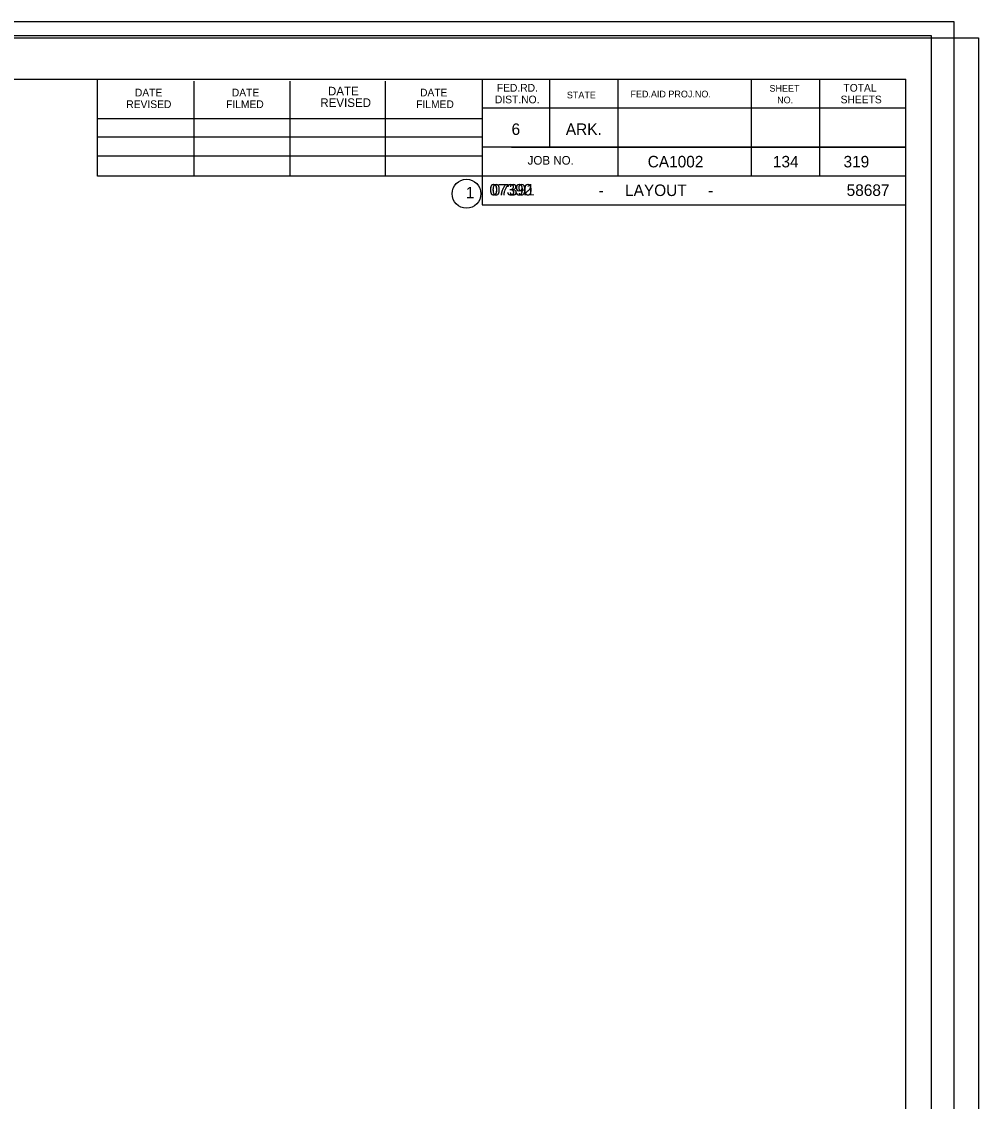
# Model space of a CAD drawing. Extents: x -290 to 969, y 225 to 885.
# Drawn here: x 451.9 to 743.9, y 555 to 884.6 of the extents above; entities that cross this region are included whole.
import ezdxf

# ---------------------------------------------------------------- set-up
doc = ezdxf.new("R2010")
doc.units = 0
for name, color, linetype in [('border', 7, 'Continuous'), ('Border 2660-Hwy18 - Level 62', 7, 'Continuous'), ('Border 2660-Hwy18 - Level 63', 7, 'Continuous'), ('Border 2660-Hwy18 - Text', 7, 'Continuous'), ('Bridge No BLFR', 7, 'Continuous'), ('Bridge No BLO', 7, 'Continuous'), ('Bridge No Ditch 81', 7, 'Continuous'), ('Level 62 PDF', 7, 'Continuous'), ('Text', 7, 'Continuous'), ('Title Text', 7, 'Continuous')]:
    doc.layers.add(name, color=color, linetype=linetype)

msp = doc.modelspace()

# ---------------------------------------------------------------- linework, layer by layer
at = {"layer": 'border'}
for p, q in [((-238.51, 867.08), (721.82, 867.08)), ((475.04, 837.45), (475.04, 867.08)), ((592.51, 867.08), (592.51, 828.7)), ((613.03, 867.08), (613.03, 846.27)), ((633.88, 867.08), (633.88, 837.45)), ((674.59, 867.08), (674.59, 837.45)), ((695.43, 867.08), (695.43, 837.45)), ((721.82, 250.72), (721.82, 867.08)), ((504.6, 837.45), (504.6, 866.5)), ((533.9, 837.45), (533.9, 866.5)), ((562.92, 837.45), (562.92, 866.5)), ((721.82, 858.26), (592.51, 858.26)), ((721.82, 858.33), (721.82, 858.33)), ((475.04, 855.02), (592.51, 855.02)), ((475.04, 849.44), (592.51, 849.44)), ((721.82, 846.27), (592.51, 846.27)), ((601.4, 846.27), (721.82, 846.27)), ((475.04, 837.45), (475.04, 843.64)), ((475.04, 843.64), (592.51, 843.64)), ((721.82, 837.45), (475.04, 837.45)), ((592.51, 828.7), (721.82, 828.7))]:
    msp.add_line(p, q, dxfattribs=at)
msp.add_circle((587.68, 832.1), 4.4, dxfattribs=at)
at = {"layer": 'Border 2660-Hwy18 - Level 62'}
msp.add_lwpolyline([(-287.11, 884.65), (736.44, 884.65), (736.44, 230.36), (-287.11, 230.36)], close=True, dxfattribs=at)
at = {"layer": 'Border 2660-Hwy18 - Level 63'}
msp.add_lwpolyline([(-290.45, 880.36), (729.54, 880.36), (729.54, 239.27), (-290.45, 239.27)], close=True, dxfattribs=at)
at = {"layer": 'Level 62 PDF'}
msp.add_lwpolyline([(-279.61, 879.65), (743.94, 879.65), (743.94, 225.36), (-279.61, 225.36)], close=True, dxfattribs=at)

# ---------------------------------------------------------------- texts
at = {"layer": 'Border 2660-Hwy18 - Text'}
for s, height, p in [('DATE', 2.345, (486.46, 861.82)), ('DATE', 2.345, (516.05, 861.82)), ('DATE', 2.637, (545.39, 862.11)), ('DATE', 2.345, (573.5, 861.82)), ('FED.RD.', 2.345, (596.94, 863.26)), ('SHEET', 2.052, (680.17, 863.26)), ('TOTAL', 2.345, (702.74, 863.26)), ('REVISED', 2.345, (483.83, 858.26)), ('FILMED', 2.345, (514.28, 858.26)), ('REVISED', 2.637, (543.05, 858.58)), ('FILMED', 2.345, (572.32, 858.26)), ('DIST.NO.', 2.345, (596.36, 859.7)), ('STATE', 2.052, (618.32, 861.21)), ('FED.AID PROJ.NO.', 2.0516, (637.73, 861.5)), ('NO.', 2.052, (682.51, 859.7)), ('SHEETS', 2.345, (701.88, 859.7)), ('6', 3.52, (601.44, 850.05)), ('ARK.', 3.516, (618, 850.05)), ('JOB NO.', 2.637, (606.34, 840.98)), ('CA1002', 3.516, (642.99, 840.14)), ('319', 3.516, (702.77, 840.14)), ('1', 3.51, (587.46, 830.68))]:
    msp.add_text(s, height=height, dxfattribs=at).set_placement(p)
at = {"layer": 'Bridge No BLFR'}
msp.add_text('07392', height=3.516, dxfattribs=at).set_placement((594.64, 831.56))
at = {"layer": 'Bridge No BLO'}
msp.add_text('07391', height=3.516, dxfattribs=at).set_placement((595.42, 831.56))
at = {"layer": 'Bridge No Ditch 81'}
msp.add_text('07390', height=3.516, dxfattribs=at).set_placement((594.67, 831.56))
at = {"layer": 'Text'}
msp.add_text('134', height=3.516, dxfattribs=at).set_placement((681.21, 840.14))
at = {"layer": 'Title Text'}
for s, height, p in [('-     LAYOUT     -', 3.5167, (627.98, 831.4)), ('58687', 3.517, (703.72, 831.43))]:
    msp.add_text(s, height=height, dxfattribs=at).set_placement(p)

doc.saveas('drawing.dxf')
